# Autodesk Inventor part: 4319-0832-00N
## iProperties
Author: Miles Ivaska
Shininess: 70.0
Length Units: 11272
Angle Units: 11286
Time Units: 11279
Mass Units: 11290
Length Display Precision: 4
Angle Display Precision: 2
Compacted: True
PropertySet Name: _Private Model Information
Created: 2001-02
Part Number: 4319-0832-00N
Material: Stainless Steel, 440C
Description: NUT, 8-32 UNC KEPS
Document SubType Name: Modeling
Designer: Miles Ivaska
Control State: 0
Master: False
Checked Out: False
PropertySet Name: Design Tracking Control
Density: 7.75
Volumn: 0.07820028819372563
Area: 1.577785810948415
PropertySet Name: Model Information
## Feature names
1. Extrusion2
2. Revolution1
3. Mirror1
4. Extrusion3
5. Extrusion5
6. Extrusion6
7. Circular Pattern1
